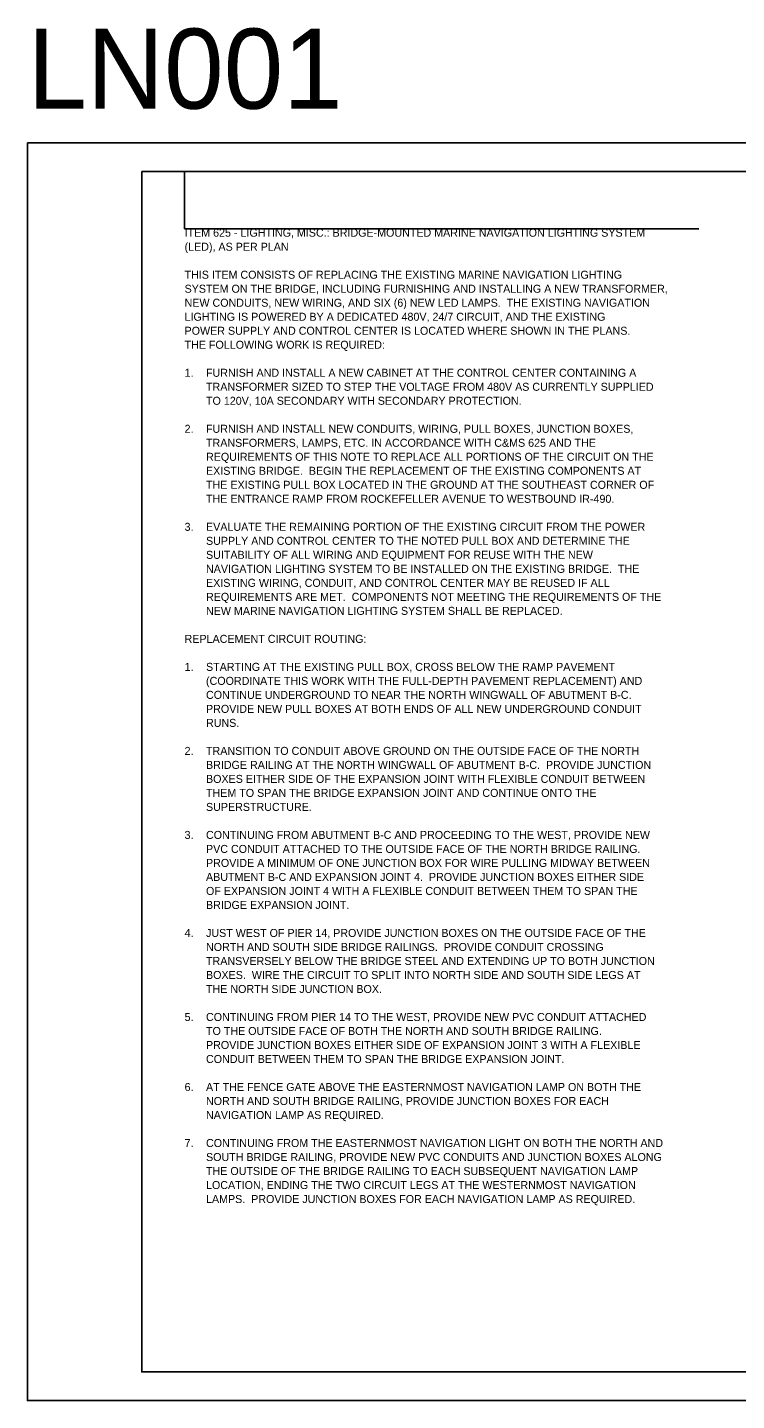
# Model space of a CAD drawing. Extents: x 0 to 34, y 26 to 50.
# Drawn here: x 0 to 12.41, y 26 to 50.02 of the extents above; entities that cross this region are included whole.
import ezdxf

# ---------------------------------------------------------------- set-up
doc = ezdxf.new("R2010")
doc.units = 0
doc.layers.add('SC_Scratch1', color=7, linetype='Continuous')
doc.layers.add('SH_Text', color=7, linetype='Continuous')

msp = doc.modelspace()

# ---------------------------------------------------------------- linework, layer by layer
at = {"layer": 'SC_Scratch1'}
for q in [(2.75, 47.5), (11.75, 46.5)]:
    msp.add_line((2.75, 46.5), q, dxfattribs=at)
for points in [[(0, 48), (34, 48), (34, 26), (0, 26)], [(2, 47.5), (32.5, 47.5), (32.5, 26.5), (2, 26.5)]]:
    msp.add_lwpolyline(points, close=True, dxfattribs=at)

# ---------------------------------------------------------------- texts
at = {"layer": 'SH_Text'}
for s, height, p in [('LN001', 1.4, (0, 48.6)), ('ITEM 625 - LIGHTING, MISC.: BRIDGE-MOUNTED MARINE NAVIGATION LIGHTING SYSTEM ', 0.14, (2.75, 46.36)), ('ITEM 625 - LIGHTING, MISC.: BRIDGE-MOUNTED MARINE NAVIGATION LIGHTING SYSTEM ', 0.14, (2.75, 46.36)), ('(LED), AS PER PLAN', 0.14, (2.75, 46.115)), ('(LED), AS PER PLAN', 0.14, (2.75, 46.115)), ('THIS ITEM CONSISTS OF REPLACING THE EXISTING MARINE NAVIGATION LIGHTING ', 0.14, (2.75, 45.625)), ('SYSTEM ON THE BRIDGE, INCLUDING FURNISHING AND INSTALLING A NEW TRANSFORMER, ', 0.14, (2.75, 45.38)), ('NEW CONDUITS, NEW WIRING, AND SIX (6) NEW LED LAMPS.  THE EXISTING NAVIGATION ', 0.14, (2.75, 45.135)), ('LIGHTING IS POWERED BY A DEDICATED 480V, 24/7 CIRCUIT, AND THE EXISTING ', 0.14, (2.75, 44.89)), ('POWER SUPPLY AND CONTROL CENTER IS LOCATED WHERE SHOWN IN THE PLANS.', 0.14, (2.75, 44.645)), ('THE FOLLOWING WORK IS REQUIRED:', 0.14, (2.75, 44.4)), ('1.', 0.14, (2.75, 43.91)), ('FURNISH AND INSTALL A NEW CABINET AT THE CONTROL CENTER CONTAINING A ', 0.14, (3.125, 43.91)), ('TRANSFORMER SIZED TO STEP THE VOLTAGE FROM 480V AS CURRENTLY SUPPLIED ', 0.14, (3.125, 43.665)), ('TO 120V, 10A SECONDARY WITH SECONDARY PROTECTION.  ', 0.14, (3.125, 43.42)), ('2.', 0.14, (2.75, 42.93)), ('FURNISH AND INSTALL NEW CONDUITS, WIRING, PULL BOXES, JUNCTION BOXES, ', 0.14, (3.125, 42.93)), ('TRANSFORMERS, LAMPS, ETC. IN ACCORDANCE WITH C&MS 625 AND THE ', 0.14, (3.125, 42.685)), ('REQUIREMENTS OF THIS NOTE TO REPLACE ALL PORTIONS OF THE CIRCUIT ON THE ', 0.14, (3.125, 42.44)), ('EXISTING BRIDGE.  BEGIN THE REPLACEMENT OF THE EXISTING COMPONENTS AT ', 0.14, (3.125, 42.195)), ('THE EXISTING PULL BOX LOCATED IN THE GROUND AT THE SOUTHEAST CORNER OF ', 0.14, (3.125, 41.95)), ('THE ENTRANCE RAMP FROM ROCKEFELLER AVENUE TO WESTBOUND IR-490.  ', 0.14, (3.125, 41.705)), ('3.', 0.14, (2.75, 41.215)), ('EVALUATE THE REMAINING PORTION OF THE EXISTING CIRCUIT FROM THE POWER ', 0.14, (3.125, 41.215)), ('SUPPLY AND CONTROL CENTER TO THE NOTED PULL BOX AND DETERMINE THE ', 0.14, (3.125, 40.97)), ('SUITABILITY OF ALL WIRING AND EQUIPMENT FOR REUSE WITH THE NEW ', 0.14, (3.125, 40.725)), ('NAVIGATION LIGHTING SYSTEM TO BE INSTALLED ON THE EXISTING BRIDGE.  THE ', 0.14, (3.125, 40.48)), ('EXISTING WIRING, CONDUIT, AND CONTROL CENTER MAY BE REUSED IF ALL ', 0.14, (3.125, 40.235)), ('REQUIREMENTS ARE MET.  COMPONENTS NOT MEETING THE REQUIREMENTS OF THE ', 0.14, (3.125, 39.99)), ('NEW MARINE NAVIGATION LIGHTING SYSTEM SHALL BE REPLACED.', 0.14, (3.125, 39.745)), ('REPLACEMENT CIRCUIT ROUTING:', 0.14, (2.75, 39.255)), ('1.', 0.14, (2.75, 38.765)), ('STARTING AT THE EXISTING PULL BOX, CROSS BELOW THE RAMP PAVEMENT ', 0.14, (3.125, 38.765)), ('(COORDINATE THIS WORK WITH THE FULL-DEPTH PAVEMENT REPLACEMENT) AND ', 0.14, (3.125, 38.52)), ('CONTINUE UNDERGROUND TO NEAR THE NORTH WINGWALL OF ABUTMENT B-C.  ', 0.14, (3.125, 38.275)), ('PROVIDE NEW PULL BOXES AT BOTH ENDS OF ALL NEW UNDERGROUND CONDUIT ', 0.14, (3.125, 38.03)), ('RUNS.', 0.14, (3.125, 37.785)), ('2.', 0.14, (2.75, 37.295)), ('TRANSITION TO CONDUIT ABOVE GROUND ON THE OUTSIDE FACE OF THE NORTH ', 0.14, (3.125, 37.295)), ('BRIDGE RAILING AT THE NORTH WINGWALL OF ABUTMENT B-C.  PROVIDE JUNCTION ', 0.14, (3.125, 37.05)), ('BOXES EITHER SIDE OF THE EXPANSION JOINT WITH FLEXIBLE CONDUIT BETWEEN ', 0.14, (3.125, 36.805)), ('THEM TO SPAN THE BRIDGE EXPANSION JOINT AND CONTINUE ONTO THE ', 0.14, (3.125, 36.56)), ('SUPERSTRUCTURE.', 0.14, (3.125, 36.315)), ('3.', 0.14, (2.75, 35.825)), ('CONTINUING FROM ABUTMENT B-C AND PROCEEDING TO THE WEST, PROVIDE NEW ', 0.14, (3.125, 35.825)), ('PVC CONDUIT ATTACHED TO THE OUTSIDE FACE OF THE NORTH BRIDGE RAILING.  ', 0.14, (3.125, 35.58)), ('PROVIDE A MINIMUM OF ONE JUNCTION BOX FOR WIRE PULLING MIDWAY BETWEEN ', 0.14, (3.125, 35.335)), ('ABUTMENT B-C AND EXPANSION JOINT 4.  PROVIDE JUNCTION BOXES EITHER SIDE ', 0.14, (3.125, 35.09)), ('OF EXPANSION JOINT 4 WITH A FLEXIBLE CONDUIT BETWEEN THEM TO SPAN THE ', 0.14, (3.125, 34.845)), ('BRIDGE EXPANSION JOINT.', 0.14, (3.125, 34.6)), ('4.', 0.14, (2.75, 34.11)), ('JUST WEST OF PIER 14, PROVIDE JUNCTION BOXES ON THE OUTSIDE FACE OF THE ', 0.14, (3.125, 34.11)), ('NORTH AND SOUTH SIDE BRIDGE RAILINGS.  PROVIDE CONDUIT CROSSING ', 0.14, (3.125, 33.865)), ('TRANSVERSELY BELOW THE BRIDGE STEEL AND EXTENDING UP TO BOTH JUNCTION ', 0.14, (3.125, 33.62)), ('BOXES.  WIRE THE CIRCUIT TO SPLIT INTO NORTH SIDE AND SOUTH SIDE LEGS AT ', 0.14, (3.125, 33.375)), ('THE NORTH SIDE JUNCTION BOX.', 0.14, (3.125, 33.13)), ('5.', 0.14, (2.75, 32.64)), ('CONTINUING FROM PIER 14 TO THE WEST, PROVIDE NEW PVC CONDUIT ATTACHED ', 0.14, (3.125, 32.64)), ('TO THE OUTSIDE FACE OF BOTH THE NORTH AND SOUTH BRIDGE RAILING.  ', 0.14, (3.125, 32.395)), ('PROVIDE JUNCTION BOXES EITHER SIDE OF EXPANSION JOINT 3 WITH A FLEXIBLE ', 0.14, (3.125, 32.15)), ('CONDUIT BETWEEN THEM TO SPAN THE BRIDGE EXPANSION JOINT.', 0.14, (3.125, 31.905)), ('6.', 0.14, (2.75, 31.415)), ('AT THE FENCE GATE ABOVE THE EASTERNMOST NAVIGATION LAMP ON BOTH THE ', 0.14, (3.125, 31.415)), ('NORTH AND SOUTH BRIDGE RAILING, PROVIDE JUNCTION BOXES FOR EACH ', 0.14, (3.125, 31.17)), ('NAVIGATION LAMP AS REQUIRED.', 0.14, (3.125, 30.925)), ('7.', 0.14, (2.75, 30.435)), ('CONTINUING FROM THE EASTERNMOST NAVIGATION LIGHT ON BOTH THE NORTH AND ', 0.14, (3.125, 30.435)), ('SOUTH BRIDGE RAILING, PROVIDE NEW PVC CONDUITS AND JUNCTION BOXES ALONG ', 0.14, (3.125, 30.19)), ('THE OUTSIDE OF THE BRIDGE RAILING TO EACH SUBSEQUENT NAVIGATION LAMP ', 0.14, (3.125, 29.945)), ('LOCATION, ENDING THE TWO CIRCUIT LEGS AT THE WESTERNMOST NAVIGATION ', 0.14, (3.125, 29.7)), ('LAMPS.  PROVIDE JUNCTION BOXES FOR EACH NAVIGATION LAMP AS REQUIRED.', 0.14, (3.125, 29.455))]:
    msp.add_text(s, height=height, dxfattribs=at).set_placement(p)

doc.saveas('drawing.dxf')
